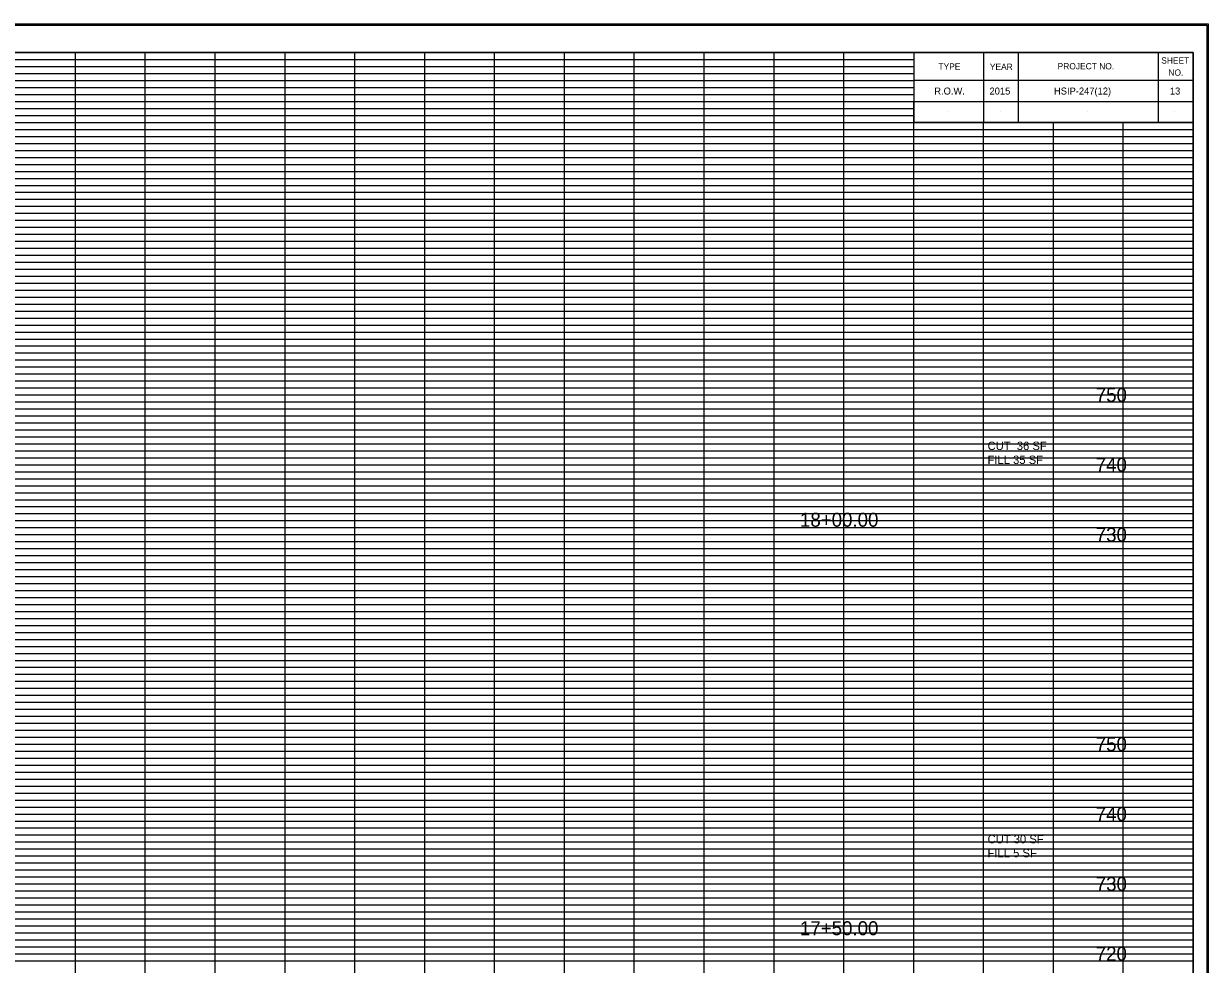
# Model space of a CAD drawing. Extents: x -200 to 1704, y -325 to 2307.
# Drawn here: x 1152.6 to 1322.2, y 1889.5 to 2024.1 of the extents above; entities that cross this region are included whole.
import ezdxf

# ---------------------------------------------------------------- set-up
doc = ezdxf.new("R2010")
doc.units = 0
for name, color, linetype in [('DESIGN - SCRATCH - User 1', 7, 'Continuous'), ('DESIGN - SHEET - Corner Text', 7, 'Continuous'), ('DESIGN - SHEET - Light Grid', 7, 'Continuous'), ('DESIGN - SHEET - Linework', 7, 'Continuous'), ('DESIGN - SHEET - Plot Shape', 7, 'Continuous'), ('DESIGN - TYPICAL - Text', 7, 'Continuous')]:
    doc.layers.add(name, color=color, linetype=linetype)

msp = doc.modelspace()

# ---------------------------------------------------------------- linework, layer by layer
at = {"layer": 'DESIGN - SCRATCH - User 1'}
for p, q in [((1285, 2014.5), (1285, 2014.5)), ((1292.4, 2014.5), (1292.4, 2014.5)), ((1304.9, 2014.5), (1304.9, 2014.5)), ((1317.4, 2014.5), (1317.4, 2014.5)), ((1285, 2011.5), (1285, 2011.5)), ((1292.4, 2011.5), (1292.4, 2011.5)), ((1304.9, 2011.5), (1304.9, 2011.5)), ((1317.4, 2011.5), (1317.4, 2011.5))]:
    msp.add_line(p, q, dxfattribs=at)
at = {"layer": 'DESIGN - SHEET - Light Grid'}
for p, q in [((1080, 2019), (1160, 2019)), ((1160, 2019), (1240, 2019)), ((1240, 2019), (1280, 2019)), ((1080, 2018), (1160, 2018)), ((1080, 2017), (1160, 2017)), ((1160, 2018), (1240, 2018)), ((1160, 2017), (1240, 2017)), ((1240, 2018), (1280, 2018)), ((1240, 2017), (1280, 2017)), ((1080, 2016), (1160, 2016)), ((1080, 2015), (1160, 2015)), ((1160, 2016), (1240, 2016)), ((1160, 2015), (1240, 2015)), ((1240, 2016), (1280, 2016)), ((1240, 2015), (1280, 2015)), ((1080, 2014), (1160, 2014)), ((1080, 2013), (1160, 2013)), ((1160, 2014), (1240, 2014)), ((1160, 2013), (1240, 2013)), ((1240, 2014), (1280, 2014)), ((1240, 2013), (1280, 2013)), ((1080, 2012), (1160, 2012)), ((1160, 2012), (1240, 2012)), ((1240, 2012), (1280, 2012)), ((1080, 2011), (1160, 2011)), ((1160, 2011), (1240, 2011)), ((1240, 2011), (1280, 2011)), ((1080, 2009), (1160, 2009)), ((1080, 2008), (1160, 2008)), ((1160, 2009), (1240, 2009)), ((1160, 2008), (1240, 2008)), ((1240, 2009), (1320, 2009)), ((1240, 2008), (1320, 2008)), ((1080, 2007), (1160, 2007)), ((1160, 2007), (1240, 2007)), ((1240, 2007), (1320, 2007)), ((1080, 2006), (1160, 2006)), ((1080, 2005), (1160, 2005)), ((1160, 2006), (1240, 2006)), ((1160, 2005), (1240, 2005)), ((1240, 2006), (1320, 2006)), ((1240, 2005), (1320, 2005)), ((1080, 2004), (1160, 2004)), ((1080, 2003), (1160, 2003)), ((1160, 2004), (1240, 2004)), ((1160, 2003), (1240, 2003)), ((1240, 2004), (1320, 2004)), ((1240, 2003), (1320, 2003)), ((1080, 2002), (1160, 2002)), ((1160, 2002), (1240, 2002)), ((1240, 2002), (1320, 2002)), ((1080, 2001), (1160, 2001)), ((1160, 2001), (1240, 2001)), ((1240, 2001), (1320, 2001)), ((1080, 1999), (1160, 1999)), ((1080, 1998), (1160, 1998)), ((1160, 1999), (1240, 1999)), ((1160, 1998), (1240, 1998)), ((1240, 1999), (1320, 1999)), ((1240, 1998), (1320, 1998)), ((1080, 1997), (1160, 1997)), ((1080, 1996), (1160, 1996)), ((1160, 1997), (1240, 1997)), ((1160, 1996), (1240, 1996)), ((1240, 1997), (1320, 1997)), ((1240, 1996), (1320, 1996)), ((1080, 1995), (1160, 1995)), ((1160, 1995), (1240, 1995)), ((1240, 1995), (1320, 1995)), ((1080, 1994), (1160, 1994)), ((1080, 1993), (1160, 1993)), ((1160, 1994), (1240, 1994)), ((1160, 1993), (1240, 1993)), ((1240, 1994), (1320, 1994)), ((1240, 1993), (1320, 1993)), ((1080, 1992), (1160, 1992)), ((1080, 1991), (1160, 1991)), ((1160, 1992), (1240, 1992)), ((1160, 1991), (1240, 1991)), ((1240, 1992), (1320, 1992)), ((1240, 1991), (1320, 1991)), ((1080, 1989), (1160, 1989)), ((1080, 1988), (1160, 1988)), ((1160, 1989), (1240, 1989)), ((1160, 1988), (1240, 1988)), ((1240, 1989), (1320, 1989)), ((1240, 1988), (1320, 1988)), ((1080, 1987), (1160, 1987)), ((1080, 1986), (1160, 1986)), ((1160, 1987), (1240, 1987)), ((1160, 1986), (1240, 1986)), ((1240, 1987), (1320, 1987)), ((1240, 1986), (1320, 1986)), ((1080, 1985), (1160, 1985)), ((1160, 1985), (1240, 1985)), ((1240, 1985), (1320, 1985)), ((1080, 1984), (1160, 1984)), ((1080, 1983), (1160, 1983)), ((1160, 1984), (1240, 1984)), ((1160, 1983), (1240, 1983)), ((1240, 1984), (1320, 1984)), ((1240, 1983), (1320, 1983)), ((1080, 1982), (1160, 1982)), ((1080, 1981), (1160, 1981)), ((1160, 1982), (1240, 1982)), ((1160, 1981), (1240, 1981)), ((1240, 1982), (1320, 1982)), ((1240, 1981), (1320, 1981)), ((1080, 1979), (1160, 1979)), ((1080, 1978), (1160, 1978)), ((1160, 1979), (1240, 1979)), ((1160, 1978), (1240, 1978)), ((1240, 1979), (1320, 1979)), ((1240, 1978), (1320, 1978)), ((1080, 1977), (1160, 1977)), ((1080, 1976), (1160, 1976)), ((1160, 1977), (1240, 1977)), ((1160, 1976), (1240, 1976)), ((1240, 1977), (1320, 1977)), ((1240, 1976), (1320, 1976)), ((1080, 1975), (1160, 1975)), ((1080, 1974), (1160, 1974)), ((1160, 1975), (1240, 1975)), ((1160, 1974), (1240, 1974)), ((1240, 1975), (1320, 1975)), ((1240, 1974), (1320, 1974)), ((1080, 1973), (1160, 1973)), ((1160, 1973), (1240, 1973)), ((1240, 1973), (1320, 1973)), ((1080, 1972), (1160, 1972)), ((1080, 1971), (1160, 1971)), ((1160, 1972), (1240, 1972)), ((1160, 1971), (1240, 1971)), ((1240, 1972), (1320, 1972)), ((1240, 1971), (1320, 1971)), ((1080, 1969), (1160, 1969)), ((1160, 1969), (1240, 1969)), ((1240, 1969), (1320, 1969)), ((1080, 1968), (1160, 1968)), ((1160, 1968), (1240, 1968)), ((1240, 1968), (1320, 1968)), ((1080, 1967), (1160, 1967)), ((1080, 1966), (1160, 1966)), ((1160, 1967), (1240, 1967)), ((1160, 1966), (1240, 1966)), ((1240, 1967), (1320, 1967)), ((1240, 1966), (1320, 1966)), ((1080, 1965), (1160, 1965)), ((1080, 1964), (1160, 1964)), ((1160, 1965), (1240, 1965)), ((1160, 1964), (1240, 1964)), ((1240, 1965), (1320, 1965)), ((1240, 1964), (1320, 1964)), ((1080, 1963), (1160, 1963)), ((1160, 1963), (1240, 1963)), ((1240, 1963), (1320, 1963)), ((1080, 1962), (1160, 1962)), ((1080, 1961), (1160, 1961)), ((1160, 1962), (1240, 1962)), ((1160, 1961), (1240, 1961)), ((1240, 1962), (1320, 1962)), ((1240, 1961), (1320, 1961)), ((1080, 1959), (1160, 1959)), ((1160, 1959), (1240, 1959)), ((1240, 1959), (1320, 1959)), ((1080, 1958), (1160, 1958)), ((1080, 1957), (1160, 1957)), ((1160, 1958), (1240, 1958)), ((1160, 1957), (1240, 1957)), ((1240, 1958), (1320, 1958)), ((1240, 1957), (1320, 1957)), ((1080, 1956), (1160, 1956)), ((1160, 1956), (1240, 1956)), ((1240, 1956), (1320, 1956)), ((1080, 1955), (1160, 1955)), ((1080, 1954), (1160, 1954)), ((1160, 1955), (1240, 1955)), ((1160, 1954), (1240, 1954)), ((1240, 1955), (1320, 1955)), ((1240, 1954), (1320, 1954)), ((1080, 1953), (1160, 1953)), ((1080, 1952), (1160, 1952)), ((1160, 1953), (1240, 1953)), ((1160, 1952), (1240, 1952)), ((1240, 1953), (1320, 1953)), ((1240, 1952), (1320, 1952)), ((1080, 1951), (1160, 1951)), ((1160, 1951), (1240, 1951)), ((1240, 1951), (1320, 1951)), ((1080, 1949), (1160, 1949)), ((1160, 1949), (1240, 1949)), ((1240, 1949), (1320, 1949)), ((1080, 1948), (1160, 1948)), ((1080, 1947), (1160, 1947)), ((1160, 1948), (1240, 1948)), ((1160, 1947), (1240, 1947)), ((1240, 1948), (1320, 1948)), ((1240, 1947), (1320, 1947)), ((1080, 1946), (1160, 1946)), ((1160, 1946), (1240, 1946)), ((1240, 1946), (1320, 1946)), ((1080, 1945), (1160, 1945)), ((1080, 1944), (1160, 1944)), ((1160, 1945), (1240, 1945)), ((1160, 1944), (1240, 1944)), ((1240, 1945), (1320, 1945)), ((1240, 1944), (1320, 1944)), ((1080, 1943), (1160, 1943)), ((1080, 1942), (1160, 1942)), ((1160, 1943), (1240, 1943)), ((1160, 1942), (1240, 1942)), ((1240, 1943), (1320, 1943)), ((1240, 1942), (1320, 1942)), ((1080, 1941), (1160, 1941)), ((1160, 1941), (1240, 1941)), ((1240, 1941), (1320, 1941)), ((1080, 1939), (1160, 1939)), ((1160, 1939), (1240, 1939)), ((1240, 1939), (1320, 1939)), ((1080, 1938), (1160, 1938)), ((1080, 1937), (1160, 1937)), ((1160, 1938), (1240, 1938)), ((1160, 1937), (1240, 1937)), ((1240, 1938), (1320, 1938)), ((1240, 1937), (1320, 1937)), ((1080, 1936), (1160, 1936)), ((1080, 1935), (1160, 1935)), ((1160, 1936), (1240, 1936)), ((1160, 1935), (1240, 1935)), ((1240, 1936), (1320, 1936)), ((1240, 1935), (1320, 1935)), ((1080, 1934), (1160, 1934)), ((1160, 1934), (1240, 1934)), ((1240, 1934), (1320, 1934)), ((1080, 1933), (1160, 1933)), ((1080, 1932), (1160, 1932)), ((1160, 1933), (1240, 1933)), ((1160, 1932), (1240, 1932)), ((1240, 1933), (1320, 1933)), ((1240, 1932), (1320, 1932)), ((1080, 1931), (1160, 1931)), ((1160, 1931), (1240, 1931)), ((1240, 1931), (1320, 1931)), ((1080, 1929), (1160, 1929)), ((1160, 1929), (1240, 1929)), ((1240, 1929), (1320, 1929)), ((1080, 1928), (1160, 1928)), ((1080, 1927), (1160, 1927)), ((1160, 1928), (1240, 1928)), ((1160, 1927), (1240, 1927)), ((1240, 1928), (1320, 1928)), ((1240, 1927), (1320, 1927)), ((1080, 1926), (1160, 1926)), ((1080, 1925), (1160, 1925)), ((1160, 1926), (1240, 1926)), ((1160, 1925), (1240, 1925)), ((1240, 1926), (1320, 1926)), ((1240, 1925), (1320, 1925)), ((1080, 1924), (1160, 1924)), ((1160, 1924), (1240, 1924)), ((1240, 1924), (1320, 1924)), ((1080, 1923), (1160, 1923)), ((1080, 1922), (1160, 1922)), ((1160, 1923), (1240, 1923)), ((1160, 1922), (1240, 1922)), ((1240, 1923), (1320, 1923)), ((1240, 1922), (1320, 1922)), ((1080, 1921), (1160, 1921)), ((1160, 1921), (1240, 1921)), ((1240, 1921), (1320, 1921)), ((1080, 1919), (1160, 1919)), ((1080, 1918), (1160, 1918)), ((1160, 1919), (1240, 1919)), ((1160, 1918), (1240, 1918)), ((1240, 1919), (1320, 1919)), ((1240, 1918), (1320, 1918)), ((1080, 1917), (1160, 1917)), ((1160, 1917), (1240, 1917)), ((1240, 1917), (1320, 1917)), ((1080, 1916), (1160, 1916)), ((1080, 1915), (1160, 1915)), ((1160, 1916), (1240, 1916)), ((1160, 1915), (1240, 1915)), ((1240, 1916), (1320, 1916)), ((1240, 1915), (1320, 1915)), ((1080, 1914), (1160, 1914)), ((1080, 1913), (1160, 1913)), ((1160, 1914), (1240, 1914)), ((1160, 1913), (1240, 1913)), ((1240, 1914), (1320, 1914)), ((1240, 1913), (1320, 1913)), ((1080, 1912), (1160, 1912)), ((1160, 1912), (1240, 1912)), ((1240, 1912), (1320, 1912)), ((1080, 1911), (1160, 1911)), ((1160, 1911), (1240, 1911)), ((1240, 1911), (1320, 1911)), ((1080, 1909), (1160, 1909)), ((1080, 1908), (1160, 1908)), ((1160, 1909), (1240, 1909)), ((1160, 1908), (1240, 1908)), ((1240, 1909), (1320, 1909)), ((1240, 1908), (1320, 1908)), ((1080, 1907), (1160, 1907)), ((1160, 1907), (1240, 1907)), ((1240, 1907), (1320, 1907)), ((1080, 1906), (1160, 1906)), ((1080, 1905), (1160, 1905)), ((1160, 1906), (1240, 1906)), ((1160, 1905), (1240, 1905)), ((1240, 1906), (1320, 1906)), ((1240, 1905), (1320, 1905)), ((1080, 1904), (1160, 1904)), ((1080, 1903), (1160, 1903)), ((1160, 1904), (1240, 1904)), ((1160, 1903), (1240, 1903)), ((1240, 1904), (1320, 1904)), ((1240, 1903), (1320, 1903)), ((1080, 1902), (1160, 1902)), ((1080, 1901), (1160, 1901)), ((1160, 1902), (1240, 1902)), ((1160, 1901), (1240, 1901)), ((1240, 1902), (1320, 1902)), ((1240, 1901), (1320, 1901)), ((1080, 1899), (1160, 1899)), ((1080, 1898), (1160, 1898)), ((1160, 1899), (1240, 1899)), ((1160, 1898), (1240, 1898)), ((1240, 1899), (1320, 1899)), ((1240, 1898), (1320, 1898)), ((1080, 1897), (1160, 1897)), ((1080, 1896), (1160, 1896)), ((1160, 1897), (1240, 1897)), ((1160, 1896), (1240, 1896)), ((1240, 1897), (1320, 1897)), ((1240, 1896), (1320, 1896)), ((1080, 1895), (1160, 1895)), ((1160, 1895), (1240, 1895)), ((1240, 1895), (1320, 1895)), ((1080, 1894), (1160, 1894)), ((1080, 1893), (1160, 1893)), ((1160, 1894), (1240, 1894)), ((1160, 1893), (1240, 1893)), ((1240, 1894), (1320, 1894)), ((1240, 1893), (1320, 1893)), ((1080, 1892), (1160, 1892)), ((1080, 1891), (1160, 1891)), ((1160, 1892), (1240, 1892)), ((1160, 1891), (1240, 1891)), ((1240, 1892), (1320, 1892)), ((1240, 1891), (1320, 1891))]:
    msp.add_line(p, q, dxfattribs=at)
at = {"layer": 'DESIGN - SHEET - Linework'}
for p, q in [((981.77, 2024.14), (1322.17, 2024.14)), ((1322.17, 2024.14), (1322.17, 1805.86)), ((1160, 1810), (1160, 2020)), ((1170, 1810), (1170, 2020)), ((1180, 1810), (1180, 2020)), ((1190, 1810), (1190, 2020)), ((1200, 1810), (1200, 2020)), ((1210, 1810), (1210, 2020)), ((1220, 1810), (1220, 2020)), ((1230, 1810), (1230, 2020)), ((1240, 1810), (1240, 2020)), ((1250, 1810), (1250, 2020)), ((1260, 1810), (1260, 2020)), ((1270, 1810), (1270, 2020)), ((1000, 2010), (1280, 2010)), ((1280, 1810), (1280, 2010)), ((1290, 1810), (1290, 2010)), ((1300, 1810), (1300, 2010)), ((1310, 1810), (1310, 2010)), ((1000, 2000), (1320, 2000)), ((1000, 1990), (1320, 1990)), ((1000, 1980), (1320, 1980)), ((1000, 1970), (1320, 1970)), ((1000, 1960), (1320, 1960)), ((1000, 1950), (1320, 1950)), ((1000, 1940), (1320, 1940)), ((1000, 1930), (1320, 1930)), ((1000, 1920), (1320, 1920)), ((1000, 1910), (1320, 1910)), ((1000, 1900), (1320, 1900)), ((1000, 1890), (1320, 1890))]:
    msp.add_line(p, q, dxfattribs=at)
for points in [[(1000, 2020), (1000, 1810), (1320, 1810), (1320, 2020), (1000, 2020)], [(1280, 2020), (1280, 2010), (1320, 2010), (1320, 2020), (1315, 2020), (1315, 2010), (1295, 2010), (1295, 2020), (1290, 2020), (1290, 2010), (1320, 2010), (1280, 2010), (1280, 2013), (1320, 2013), (1320, 2016), (1280, 2016)]]:
    msp.add_lwpolyline(points, dxfattribs=at)
at = {"layer": 'DESIGN - SHEET - Plot Shape'}
for points in [[(981.97, 2023.94), (1321.97, 2023.94), (1321.97, 1806.06), (981.97, 1806.06)], [(991.5, 2020), (1320, 2020), (1320, 1807.5), (991.5, 1807.5)]]:
    msp.add_lwpolyline(points, close=True, dxfattribs=at)

# ---------------------------------------------------------------- texts
at = {"layer": 'DESIGN - SHEET - Corner Text'}
for s, height, p in [('TYPE', 0.9, (1283.54, 2017.56)), ('YEAR', 0.9, (1290.9, 2017.52)), ('PROJECT NO.', 0.9, (1300.6, 2017.6)), ('SHEET', 0.9, (1315.43, 2018.43)), ('NO.', 0.9, (1316.46, 2016.69)), ('R.O.W.', 1, (1282.94, 2014)), ('2015', 1, (1290.85, 2014)), ('HSIP-247(12)', 1, (1300.08, 2014)), ('13', 1, (1316.67, 2014))]:
    msp.add_text(s, height=height, dxfattribs=at).set_placement(p)
at = {"layer": 'DESIGN - TYPICAL - Text'}
for s, height, p in [('     750     ', 2, (1302.34, 1970)), ('CUT  36 SF', 1.2, (1290.57, 1963.11)), ('FILL 35 SF', 1.2, (1290.57, 1961.11)), ('     740     ', 2, (1302.34, 1960)), ('     18+00.00     ', 2, (1260, 1952.13)), ('     730     ', 2, (1302.34, 1950)), ('     750     ', 2, (1302.34, 1920)), ('     740     ', 2, (1302.34, 1910)), ('CUT 30 SF', 1.2, (1290.57, 1906.81)), ('FILL 5 SF', 1.2, (1290.57, 1904.81)), ('     730     ', 2, (1302.34, 1900)), ('     17+50.00     ', 2, (1260, 1893.65)), ('     720     ', 2, (1302.34, 1890))]:
    msp.add_text(s, height=height, dxfattribs=at).set_placement(p)

doc.saveas('drawing.dxf')
